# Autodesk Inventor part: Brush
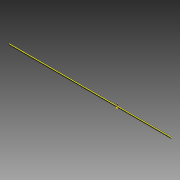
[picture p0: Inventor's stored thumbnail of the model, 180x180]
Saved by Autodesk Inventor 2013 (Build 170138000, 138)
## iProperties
Created: 2006-03
Part Number: Brush
Document SubType Name: Modeling
Designer: debonom
Material: Silicone
Mass: 8.74327 g
Surface Area: 94.4143 cm^2
Volume: 6.99461 cm^3
Density: 1.25 g/cm^3
Author: debonom
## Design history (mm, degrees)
sketch "Sketch1"
  geometry: L1 (0, 0)-(-2.332, 5); L2 (-2.332, 5)-(2.332, 5); L3 (2.332, 5)-(0, 0)
  constraints: 6 end point, 1 equal length, 1 horizontal
  dimensions: "d0" = 5 distance from line of L2 L1.start; "d2" = 50 deg angle of L3 L1
extrude "Extrusion1" new body sketch "Sketch1" distance "d3" = 200; taper "d4" = 0 deg
extrude "Extrusion2" join sketch "Sketch1" distance "d5" = 400; taper "d6" = 0 deg
sketch "Sketch2"
  geometry: L1 (0, -2.5)-(0, 15) reference; L2 (-200, 5)-(400, 5) reference; C1 r 2.5 at (0, 10); 1 further point
  constraints: 1 centre point, 1 point on line
  dimensions: "d7" = 5 distance from line of C1.centre L2; "d8" = 5 diameter of C1
workaxis "Work Axis2"
workpoint "Work Point1"
body "Solid1"
